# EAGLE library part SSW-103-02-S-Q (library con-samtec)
THROUGH-HOLE .025" SQ POST SOCKET Source: Samtec SSW.pdf
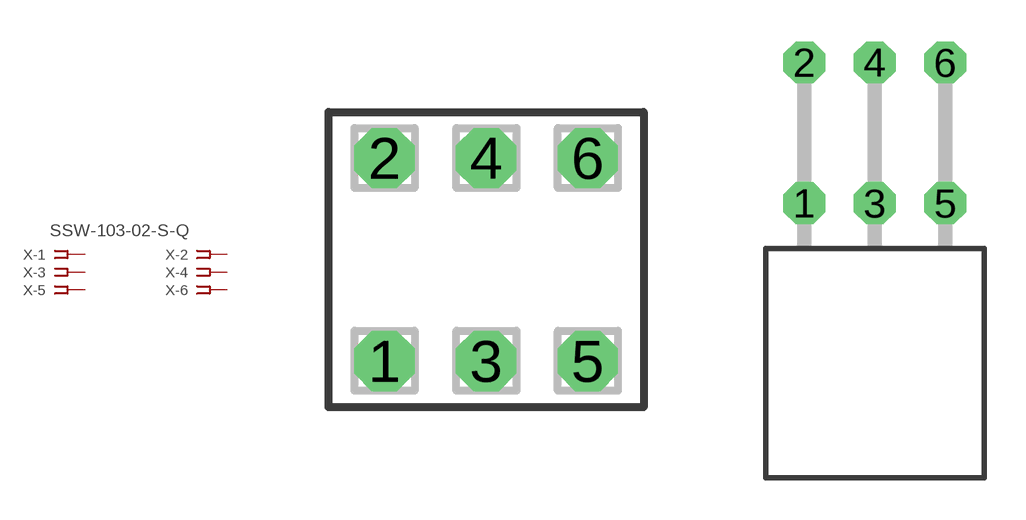
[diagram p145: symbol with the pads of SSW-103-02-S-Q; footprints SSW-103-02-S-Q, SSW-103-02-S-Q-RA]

Designator prefix X; gates -1=FPINV -2=FPIN -3=FPIN -4=FPIN -5=FPIN -6=FPIN

## SSW-103-02-S-Q (MPN: SSW-103-02-S-Q; OC_FARNELL: unknown; OC_NEWARK: 82P2073)  [SSW-103-02-S-Q]
1  -1:1  pas
2  -2:1  pas
3  -3:1  pas
4  -4:1  pas
5  -5:1  pas
6  -6:1  pas

## SSW-103-02-S-QRA (MPN: SSW-103-02-S-Q-RA; OC_FARNELL: unknown; OC_NEWARK: 82P2074)  [SSW-103-02-S-Q-RA]
Pads as for SSW-103-02-S-Q

## Footprint SSW-103-02-S-Q (pad centres in mm)
THROUGH-HOLE .025" SQ POST SOCKET Source: Samtec SSW.pdf
drill 1 pad 1.5 octagon: 1 -2.54,-2.54; 2 -2.54,2.54; 3 0,-2.54; 4 0,2.54; 5 2.54,-2.54; 6 2.54,2.54

## Footprint SSW-103-02-S-Q-RA (pad centres in mm)
THROUGH-HOLE .025" SQ POST SOCKET Source: Samtec SSW.pdf
drill 1 pad 1.5 octagon: 1 -2.54,1.524; 2 -2.54,6.604; 3 0,1.524; 4 0,6.604; 5 2.54,1.524; 6 2.54,6.604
